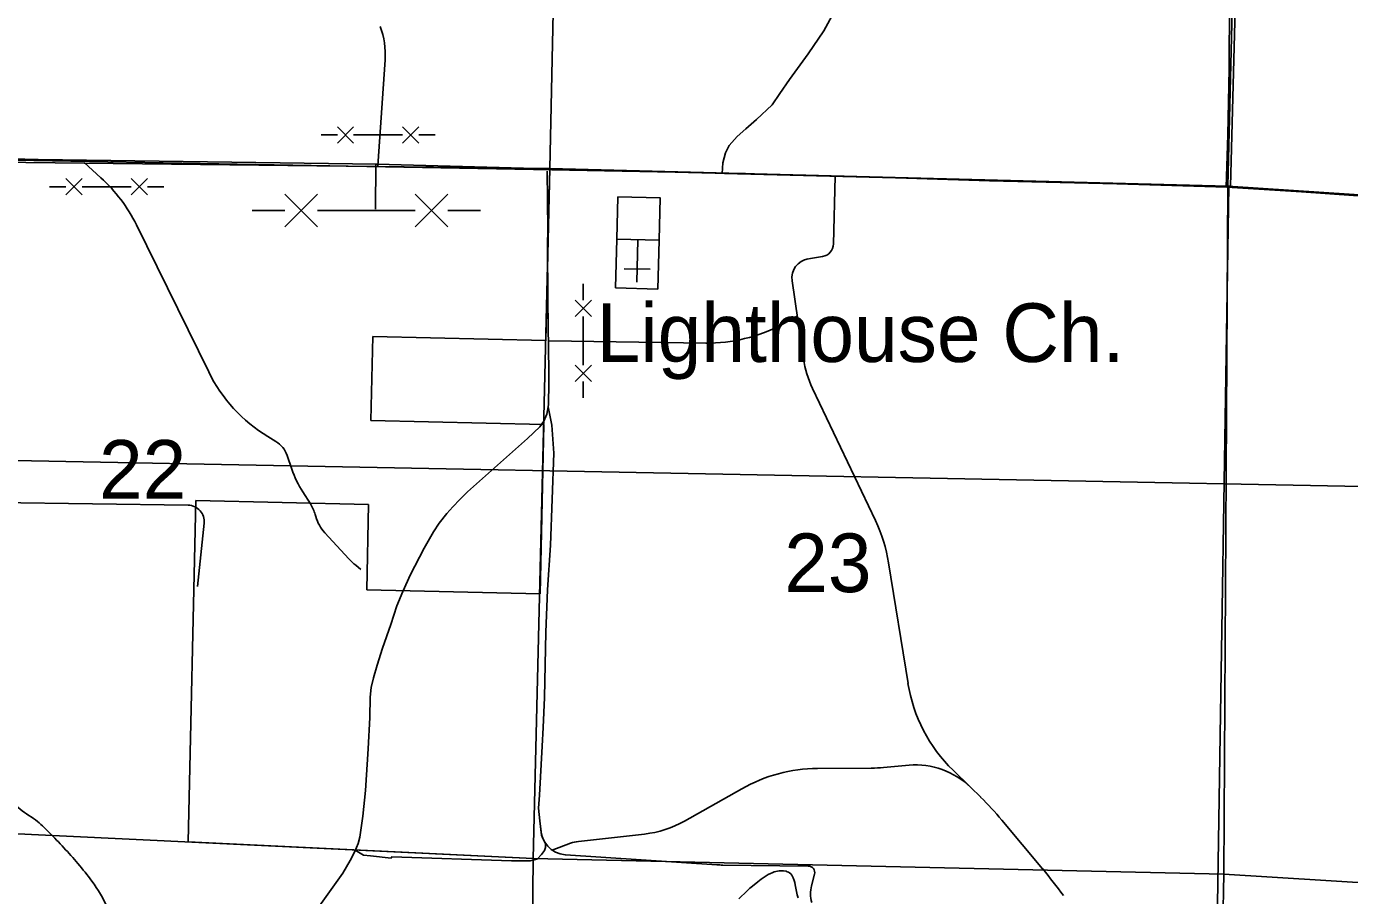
# Model space of a CAD drawing. Extents: x 1219626 to 1426462, y 456797 to 752399.
# Drawn here: x 1265814 to 1275963, y 640071 to 646739 of the extents above; entities that cross this region are included whole.
import ezdxf

# ---------------------------------------------------------------- set-up
doc = ezdxf.new("R2010")
doc.units = 0
for name, color, linetype in [('Culture', 7, 'Continuous'), ('Culture Text', 7, 'Continuous'), ('Lakes and Ponds', 7, 'Continuous'), ('Local Roads Improved', 7, 'Continuous'), ('Local Roads Paved', 7, 'Continuous'), ('Local Roads Unimproved', 7, 'Continuous'), ('Masks', 7, 'Continuous'), ('Narrow River Creek and Branch and Slough', 7, 'Continuous'), ('Quad Borders', 7, 'Continuous'), ('Section Lines', 7, 'Continuous'), ('Section Numbers', 7, 'Continuous'), ('State Forest', 7, 'Continuous'), ('Uninventoried Roads and Features', 7, 'Continuous')]:
    doc.layers.add(name, color=color, linetype=linetype)

msp = doc.modelspace()

# ---------------------------------------------------------------- linework, layer by layer
at = {"layer": 'Culture'}
for p, q in [((1270343, 645107), (1270333, 644733)), ((1270667, 645099), (1270343, 645107)), ((1270505, 645103), (1270497, 644778)), ((1270658, 644724), (1270667, 645099)), ((1270599, 644876), (1270399, 644881)), ((1270333, 644733), (1270658, 644724))]:
    msp.add_line(p, q, dxfattribs=at)
msp.add_lwpolyline([(1270667, 645099), (1270343, 645107), (1270351, 645432), (1270676, 645424)], close=True, dxfattribs=at)
at = {"layer": 'Lakes and Ponds'}
msp.add_lwpolyline([(1271733, 640054), (1271727, 640076), (1271712, 640153), (1271708, 640172), (1271703, 640186), (1271695, 640207), (1271684, 640227), (1271677, 640237), (1271668, 640244), (1271659, 640250), (1271650, 640254), (1271641, 640257), (1271622, 640260), (1271605, 640261), (1271589, 640260), (1271575, 640258), (1271551, 640252), (1271534, 640246), (1271521, 640241), (1271504, 640232), (1271488, 640223), (1271451, 640197), (1271424, 640177), (1271383, 640144), (1271363, 640127), (1271343, 640108), (1271278, 640046)], dxfattribs=at)
at = {"layer": 'Local Roads Improved'}
for p, q in [((1275037, 645513), (1274854, 633899)), ((1268046, 645202), (1267796, 645452)), ((1267796, 645202), (1268046, 645452)), ((1269046, 645202), (1268796, 645452)), ((1268796, 645202), (1269046, 645452)), ((1267796, 645327), (1267546, 645327)), ((1268796, 645327), (1268046, 645327)), ((1269296, 645327), (1269046, 645327))]:
    msp.add_line(p, q, dxfattribs=at)
for points in [[(1272025, 646879), (1271931, 646706), (1271810, 646529), (1271667, 646332), (1271593, 646224), (1271534, 646138), (1271413, 646026), (1271333, 645955), (1271267, 645894), (1271205, 645825), (1271176, 645771), (1271155, 645694), (1271150, 645612)], [(1270687, 645623), (1269627, 645653), (1268501, 645683), (1265903, 645719), (1264988, 645742)], [(1268336, 640418), (1268400, 640381), (1268454, 640375), (1268611, 640358), (1268616, 640368), (1269535, 640337), (1269679, 640337), (1269731, 640351), (1269766, 640386), (1269787, 640417), (1269796, 640440), (1269796, 640468), (1269776, 640510), (1269764, 640534), (1269752, 640644), (1269743, 640742), (1269750, 640840), (1269769, 641216), (1269778, 641361), (1269787, 641590), (1269797, 642091), (1269811, 642416), (1269834, 642760), (1269860, 643466), (1269845, 643679), (1269816, 643820)]]:
    msp.add_lwpolyline(points, dxfattribs=at)
at = {"layer": 'Local Roads Paved'}
for p, q in [((1271169, 645612), (1275004, 645515)), ((1275055, 645512), (1278707, 645264))]:
    msp.add_line(p, q, dxfattribs=at)
for points in [[(1275017, 645507), (1275031, 645909), (1275039, 646414), (1275043, 646936)], [(1268049, 639975), (1268242, 640243), (1268298, 640340), (1268332, 640410), (1268358, 640471), (1268372, 640519), (1268394, 640680), (1268415, 640878), (1268435, 641196), (1268447, 641438), (1268450, 641594), (1268458, 641667), (1268477, 641741), (1268504, 641839), (1268546, 641970), (1268608, 642151), (1268656, 642293), (1268700, 642405), (1268737, 642484), (1268757, 642528), (1268864, 642737), (1268936, 642861), (1268980, 642927), (1269038, 643002), (1269086, 643054), (1269139, 643111), (1269198, 643168), (1269658, 643579), (1269752, 643667), (1269783, 643711), (1269807, 643765), (1269819, 643837), (1269820, 644008), (1269820, 644091), (1269817, 644446), (1269813, 644636), (1269812, 645067), (1269813, 645177), (1269810, 645408), (1269809, 645630)], [(1270687, 645623), (1271403, 645605), (1272245, 645586), (1273202, 645556), (1274179, 645531), (1275022, 645507), (1275596, 645471), (1276212, 645428), (1276753, 645389), (1277993, 645307), (1278703, 645263)]]:
    msp.add_lwpolyline(points, dxfattribs=at)
msp.add_arc((1274973, 644315), 1200, 86.1029, 88.5516, dxfattribs=at)
at = {"layer": 'Local Roads Unimproved'}
msp.add_line((1268493, 645683), (1268491, 645337), dxfattribs=at)
at = {"layer": 'Masks'}
for p, q in [((1269844, 645639), (1261882, 645781)), ((1269845, 645639), (1271331, 645611))]:
    msp.add_line(p, q, dxfattribs=at)
for points in [[(1275184, 654344), (1275186, 650665), (1275049, 645514)], [(1268153, 640430), (1269702, 640356), (1269830, 645649)]]:
    msp.add_lwpolyline(points, dxfattribs=at)
at = {"layer": 'Narrow River Creek and Branch and Slough'}
msp.add_spline([(1254406, 639029), (1254560, 639061), (1254684, 639099), (1254799, 639147), (1254943, 639224), (1255068, 639243), (1255297, 639243), (1255566, 639243), (1255728, 639233), (1255977, 639157), (1256159, 639023), (1256207, 638927), (1256380, 638802), (1256600, 638697), (1256839, 638706), (1257002, 638668), (1257194, 638687), (1257395, 638735), (1257548, 638802), (1257740, 638783), (1258008, 638726), (1258247, 638706), (1258487, 638611), (1258765, 638534), (1258908, 638534), (1259042, 638543), (1259263, 638553), (1259473, 638668), (1259684, 638812), (1259828, 638908), (1259981, 638956), (1260182, 638956), (1260441, 638994), (1260958, 639138), (1261284, 639233), (1261542, 639320), (1261628, 639358), (1261734, 639425), (1261849, 639511), (1262021, 639559), (1262184, 639598), (1262280, 639713), (1262385, 639866), (1262471, 639981), (1262577, 640077), (1262701, 640211), (1262701, 640336), (1262701, 640441), (1262806, 640594), (1262941, 640690), (1262960, 640776), (1262969, 640901), (1263008, 640987), (1263036, 641073), (1263151, 641131), (1263317, 641303), (1263384, 641370), (1263451, 641437), (1263489, 641437), (1263556, 641523), (1263738, 641638), (1264007, 641705), (1264275, 641715), (1264495, 641629), (1264715, 641533), (1264859, 641437), (1264974, 641332), (1265108, 641245), (1265242, 641188), (1265386, 641140), (1265482, 641073), (1265510, 641054), (1265577, 641015), (1265644, 640900), (1265750, 640747), (1265884, 640651), (1265989, 640555), (1266209, 640316), (1266315, 640182), (1266439, 639971), (1266525, 639837), (1266640, 639798), (1266727, 639750), (1266995, 639406), (1267119, 639252), (1267148, 639118), (1267158, 639022), (1267330, 638888), (1267512, 638763), (1267694, 638639), (1267838, 638572)], degree=3, dxfattribs=at)
at = {"layer": 'Quad Borders'}
msp.add_line((1300990, 642732), (1261728, 643485), dxfattribs=at)
at = {"layer": 'Section Lines'}
for p, q in [((1269937, 650778), (1269830, 645649)), ((1275029, 645515), (1275162, 650666)), ((1264516, 645711), (1269830, 645649)), ((1269830, 645649), (1269702, 640356)), ((1269830, 645649), (1275029, 645515)), ((1274998, 640236), (1275029, 645515)), ((1275029, 645515), (1280281, 645167)), ((1269702, 640356), (1264402, 640609)), ((1269702, 640356), (1269646, 635124)), ((1274998, 640236), (1269702, 640356)), ((1274915, 634957), (1274998, 640236)), ((1280211, 639906), (1274998, 640236))]:
    msp.add_line(p, q, dxfattribs=at)
at = {"layer": 'State Forest'}
for p, q in [((1269830, 645649), (1269937, 650778)), ((1269798, 644331), (1269830, 645649)), ((1268456, 643716), (1268470, 644361)), ((1268470, 644361), (1269798, 644331)), ((1269783, 643686), (1268456, 643716)), ((1269756, 642386), (1269783, 643686)), ((1267054, 640482), (1267113, 643101)), ((1267113, 643101), (1268439, 643071)), ((1268439, 643071), (1268424, 642416)), ((1268424, 642416), (1269756, 642386)), ((1269702, 640356), (1267054, 640482)), ((1269675, 637753), (1269702, 640356))]:
    msp.add_line(p, q, dxfattribs=at)
at = {"layer": 'Uninventoried Roads and Features'}
for p, q in [((1268509, 645670), (1268566, 646483)), ((1268199, 645907), (1268074, 645907)), ((1268324, 645844), (1268199, 645969)), ((1268199, 645844), (1268324, 645969)), ((1268699, 645907), (1268324, 645907)), ((1268824, 645844), (1268699, 645969)), ((1268699, 645844), (1268824, 645969)), ((1268949, 645907), (1268824, 645907)), ((1266385, 645578), (1266256, 645695)), ((1266117, 645510), (1265992, 645510)), ((1266242, 645448), (1266117, 645573)), ((1266117, 645448), (1266242, 645573)), ((1266617, 645510), (1266242, 645510)), ((1266742, 645448), (1266617, 645573)), ((1266617, 645448), (1266742, 645573)), ((1266867, 645510), (1266742, 645510)), ((1272005, 645070), (1272017, 645590)), ((1267212, 644089), (1266657, 645217)), ((1271812, 644957), (1271920, 644974)), ((1271775, 644190), (1271687, 644787)), ((1270085, 644640), (1270085, 644765)), ((1270023, 644515), (1270148, 644640)), ((1270023, 644640), (1270148, 644515)), ((1270085, 644140), (1270085, 644515)), ((1271605, 644451), (1271727, 644516)), ((1269824, 644326), (1271025, 644310)), ((1270023, 644015), (1270148, 644140)), ((1270023, 644140), (1270148, 644015)), ((1270085, 643890), (1270085, 644015)), ((1272327, 642948), (1271844, 643962)), ((1271868, 643911), (1271869, 643911)), ((1267728, 643554), (1267665, 643593)), ((1267849, 643343), (1267813, 643448)), ((1267993, 643077), (1267934, 643168)), ((1264494, 643103), (1267055, 643066)), ((1268034, 642979), (1268029, 642995)), ((1267177, 642928), (1267125, 642442)), ((1268288, 642655), (1268103, 642855)), ((1268378, 642574), (1268340, 642606)), ((1272577, 641699), (1272428, 642623)), ((1271882, 641046), (1272295, 641049)), ((1272388, 641054), (1272585, 641071)), ((1273056, 640902), (1272922, 641032)), ((1270861, 640642), (1271301, 640891)), ((1273056, 640902), (1273134, 640825)), ((1273296, 640650), (1273609, 640275)), ((1270048, 640486), (1270556, 640543)), ((1269847, 640419), (1269988, 640472)), ((1271110, 640306), (1269948, 640384)), ((1271811, 640297), (1271155, 640305)), ((1271837, 640146), (1271859, 640235))]:
    msp.add_line(p, q, dxfattribs=at)
for centre, radius, start, end in [((1267967, 646525), 600, 355.9877, 20.9765), ((1265580, 644688), 1200, 26.1615, 47.8984), ((1271905, 645073), 100, 278.9027, 358.6501), ((1271835, 644809), 150, 98.9027, 188.3624), ((1271040, 645510), 1200, 269.2637, 298.0482), ((1272566, 644306), 800, 188.3624, 205.465), ((1268289, 644618), 1200, 206.1615, 238.7018), ((1267624, 643384), 200, 18.824, 58.7018), ((1268607, 643601), 800, 198.824, 212.7523), ((1267053, 642941), 125, 353.8896, 89.1609), ((1267740, 642914), 300, 15.5312, 32.7523), ((1268323, 643059), 300, 195.5312, 222.8265), ((1271243, 642432), 1200, 9.1511, 25.465), ((1268728, 643063), 600, 222.8265, 229.6969), ((1273761, 641890), 1200, 189.1511, 225.6176), ((1271892, 639846), 1200, 90.4895, 119.4761), ((1272285, 642249), 1200, 270.4895, 274.9167), ((1272636, 640473), 600, 45.6176, 94.9167), ((1271455, 639110), 2400, 39.9065, 45.6176), ((1270467, 641338), 800, 276.3707, 299.4761), ((1269961, 640584), 200, 178.0118, 266.184), ((1270076, 640238), 250, 96.3707, 110.5616), ((1271164, 641105), 800, 266.184, 269.348), ((1271811, 640247), 50, 345.8802, 89.348), ((1270848, 637966), 3600, 35.7903, 39.9065), ((1272079, 640085), 250, 165.8802, 195.4783)]:
    msp.add_arc(centre, radius, start, end, dxfattribs=at)

# ---------------------------------------------------------------- texts
at = {"layer": 'Culture Text'}
msp.add_text('Lighthouse Ch.', height=450, rotation=359.9998, dxfattribs=at).set_placement((1270188, 644165))
at = {"layer": 'Section Numbers'}
for s, p in [('22', (1266371, 643116)), ('23', (1271627, 642399))]:
    msp.add_text(s, height=450, rotation=359.9998, dxfattribs=at).set_placement(p)

doc.saveas('drawing.dxf')
